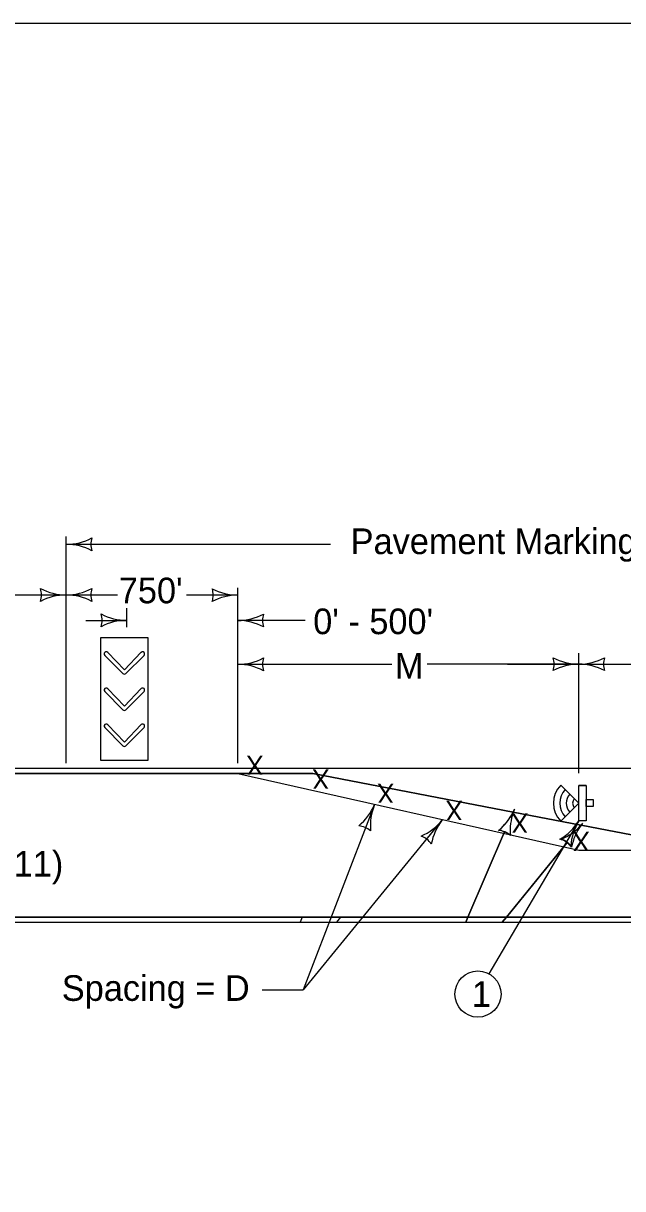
# Model space of a CAD drawing. Extents: x -2135039 to 114557, y -2139150 to -409929.
# Drawn here: x -2133449 to -2132982, y -2137945 to -2137036 of the extents above; entities that cross this region are included whole.
import ezdxf

# ---------------------------------------------------------------- set-up
doc = ezdxf.new("R2010")
doc.units = 0
for name, color, linetype in [('dsnStdLabel', 7, 'Continuous'), ('dsnStdLineWork', 7, 'Continuous'), ('dsnStdShading', 7, 'Continuous'), ('Level 1', 7, 'Continuous'), ('Level 2', 7, 'Continuous'), ('StdDimension', 7, 'Continuous')]:
    doc.layers.add(name, color=color, linetype=linetype)

msp = doc.modelspace()

# ---------------------------------------------------------------- linework, layer by layer
at = {"layer": 'dsnStdLabel'}
for p, q in [((-2133369.21, -2137542.89), (-2133355.12, -2137528.8)), ((-2133369.21, -2137571.13), (-2133355.12, -2137557.04)), ((-2133369.21, -2137599.19), (-2133355.12, -2137585.1)), ((-2133010.55, -2137630.23), (-2133010.55, -2137657.73))]:
    msp.add_line(p, q, dxfattribs=at)
for points in [[(-2133352.04, -2137514.75), (-2133352.04, -2137610.75), (-2133388.75, -2137610.75), (-2133388.75, -2137514.75)], [(-2133016.17, -2137657.73), (-2133016.17, -2137630.23), (-2133010.55, -2137630.23), (-2133010.55, -2137657.73)], [(-2133010.55, -2137646.68), (-2133010.55, -2137641.06), (-2133004.92, -2137641.06), (-2133004.92, -2137646.68)]]:
    msp.add_lwpolyline(points, close=True, dxfattribs=at)
for points in [[(-2133385.7, -2137528.77), (-2133385.65, -2137528.82), (-2133371.57, -2137542.9), (-2133371.55, -2137542.92)], [(-2133357.44, -2137526.46), (-2133357.5, -2137526.53), (-2133370.4, -2137540.1), (-2133383.3, -2137526.51)], [(-2133385.7, -2137557), (-2133385.65, -2137557.05), (-2133371.57, -2137571.14), (-2133371.55, -2137571.15)], [(-2133357.44, -2137554.7), (-2133357.5, -2137554.76), (-2133370.4, -2137568.33), (-2133383.3, -2137554.75)], [(-2133385.7, -2137585.07), (-2133385.65, -2137585.12), (-2133371.57, -2137599.2), (-2133371.55, -2137599.22)], [(-2133357.44, -2137582.76), (-2133357.5, -2137582.83), (-2133370.4, -2137596.4), (-2133383.3, -2137582.81)]]:
    msp.add_lwpolyline(points, dxfattribs=at)
for centre, start, end in [((-2133384.51, -2137527.63), 42.63982, 223.799), ((-2133356.28, -2137527.63), 314.71897, 134.90254), ((-2133370.4, -2137541.75), 225.39017, 315.83844), ((-2133384.51, -2137555.86), 42.63982, 223.799), ((-2133356.28, -2137555.86), 314.71897, 134.90254), ((-2133370.4, -2137569.98), 225.39017, 315.83844), ((-2133384.51, -2137583.93), 42.63982, 223.799), ((-2133356.28, -2137583.93), 314.71897, 134.90254), ((-2133370.4, -2137598.05), 225.39017, 315.83844)]:
    msp.add_arc(centre, 1.65, start, end, dxfattribs=at)
at = {"layer": 'dsnStdLineWork'}
for p, q in [((-2134890.21, -2137620.91), (-2133281.94, -2137620.91)), ((-2133281.94, -2137620.91), (-2133016.17, -2137680.64)), ((-2133016.17, -2137680.64), (-2132867.99, -2137680.64)), ((-2134898.17, -2137732.92), (-2132869.81, -2137732.92))]:
    msp.add_line(p, q, dxfattribs=at)
at = {"layer": 'dsnStdShading'}
for p, q in [((-2132633.8, -2137616.91), (-2133464.46, -2137616.91)), ((-2133223.54, -2137620.91), (-2133464.46, -2137620.91)), ((-2133464.46, -2137620.91), (-2133223.54, -2137620.91)), ((-2133067.38, -2137650.93), (-2133223.54, -2137620.91)), ((-2133223.54, -2137620.91), (-2133067.38, -2137650.93)), ((-2133067.24, -2137650.96), (-2133014.49, -2137661.1)), ((-2133014.49, -2137661.1), (-2133067.24, -2137650.96)), ((-2133073.99, -2137666.4), (-2133102.64, -2137732.92)), ((-2133102.63, -2137732.91), (-2133073.99, -2137666.4)), ((-2133014.39, -2137661.12), (-2132912.87, -2137680.64)), ((-2132912.87, -2137680.64), (-2133014.39, -2137661.12)), ((-2133072.64, -2137732.92), (-2133025.35, -2137674.56)), ((-2133025.35, -2137674.56), (-2133072.64, -2137732.92)), ((-2133102.63, -2137732.91), (-2134898.19, -2137732.91)), ((-2134894.19, -2137736.9), (-2133075.86, -2137736.9)), ((-2134894.19, -2137736.91), (-2133104.35, -2137736.9)), ((-2133680.95, -2137732.91), (-2133102.63, -2137732.91)), ((-2133231.88, -2137732.91), (-2133233.49, -2137736.9)), ((-2133233.49, -2137736.9), (-2133204.94, -2137736.9)), ((-2133201.81, -2137732.91), (-2133231.88, -2137732.91)), ((-2133204.94, -2137736.9), (-2133201.81, -2137732.91)), ((-2133104.35, -2137736.9), (-2133102.63, -2137732.91)), ((-2133102.63, -2137732.91), (-2133104.35, -2137736.9)), ((-2133104.35, -2137736.9), (-2133075.86, -2137736.9)), ((-2133102.64, -2137732.92), (-2133072.64, -2137732.92)), ((-2133072.62, -2137732.91), (-2133102.63, -2137732.91)), ((-2133072.62, -2137732.91), (-2133075.86, -2137736.9)), ((-2133075.86, -2137736.9), (-2133072.62, -2137732.91)), ((-2133075.86, -2137736.9), (-2132839.34, -2137736.9)), ((-2132836.36, -2137732.91), (-2133072.62, -2137732.91))]:
    msp.add_line(p, q, dxfattribs=at)
for points in [[(-2133066.76, -2137649.6), (-2133066.39, -2137648.74), (-2133066.39, -2137648.74)], [(-2133066.74, -2137649.61), (-2133066.76, -2137649.6)], [(-2133014.39, -2137661.12), (-2133014.49, -2137661.1)], [(-2133013.65, -2137660.12), (-2133013.26, -2137659.63), (-2133013.25, -2137659.63)], [(-2133072.64, -2137732.92), (-2132863.84, -2137732.92), (-2132768.77, -2137732.92)]]:
    msp.add_lwpolyline(points, dxfattribs=at)
for centre, radius, start, end in [((-2133105.61, -2137632.37), 42.5, 309.26549, 336.07196), ((-2133105.61, -2137632.37), 42.5, 334.0959, 336.07196), ((-2133027.17, -2137665.12), 42.5, 157.35558, 160.5422), ((-2133027.17, -2137665.12), 42.5, 158.60338, 160.5422), ((-2133105.61, -2137632.37), 42.5, 337.32038, 337.33798), ((-2133105.61, -2137632.37), 42.5, 309.26549, 334.0959), ((-2133027.17, -2137665.12), 42.5, 160.5422, 185.41047), ((-2133027.17, -2137665.12), 42.5, 160.5422, 185.41047), ((-2133080.12, -2137681.62), 16.42, 68.07923, 85.07133), ((-2133080.12, -2137681.62), 16.42, 49.60463, 85.07133), ((-2133080.12, -2137681.62), 16.42, 49.60463, 68.07923), ((-2133046.47, -2137633.12), 42.5, 293.33927, 318.82188), ((-2133046.47, -2137633.12), 42.5, 293.33927, 318.82188), ((-2132980.04, -2137686.14), 42.5, 143.94153, 169.48425), ((-2132980.04, -2137686.14), 42.5, 143.94153, 169.48425), ((-2133046.47, -2137633.12), 42.5, 318.82188, 320.56149), ((-2132980.04, -2137686.14), 42.5, 141.42936, 143.94153), ((-2133046.47, -2137633.12), 42.5, 321.39416, 321.41176), ((-2133035.48, -2137687.48), 16.42, 51.90955, 69.14511), ((-2133035.48, -2137687.48), 16.42, 33.67841, 69.14511), ((-2133035.48, -2137687.48), 16.42, 33.67841, 51.90955)]:
    msp.add_arc(centre, radius, start, end, dxfattribs=at)
at = {"layer": 'Level 1'}
msp.add_lwpolyline([(-2134934.44, -2137035.95), (-2131799.45, -2137035.95), (-2131799.45, -2139045.94), (-2134934.44, -2139045.94)], close=True, dxfattribs=at)
msp.add_circle((-2133094.8, -2137792.82), 18, dxfattribs=at)
at = {"layer": 'Level 2'}
for p, q in [((-2133030.31, -2137629.84), (-2133016.17, -2137643.98)), ((-2133010.55, -2137630.23), (-2133016.17, -2137630.23)), ((-2133016.17, -2137643.98), (-2133030.31, -2137658.13)), ((-2133010.55, -2137657.73), (-2133016.17, -2137657.73))]:
    msp.add_line(p, q, dxfattribs=at)
for radius, start, end in [(20.32, 135.88004, 224.03126), (15.33, 136.16647, 223.71595), (10.34, 136.72938, 223.09626), (5.32, 138.70055, 221.29945)]:
    msp.add_arc((-2133015.71, -2137644.01), radius, start, end, dxfattribs=at)
at = {"layer": 'StdDimension'}
for p, q in [((-2133415.82, -2137612.78), (-2133415.82, -2137436.14)), ((-2133209.84, -2137442.2), (-2133415.75, -2137442.2)), ((-2133281.94, -2137612.78), (-2133281.94, -2137476.08)), ((-2133518.81, -2137481.63), (-2133415.82, -2137481.63)), ((-2133415.82, -2137481.63), (-2133375.82, -2137481.63)), ((-2133321.94, -2137481.63), (-2133281.94, -2137481.63)), ((-2133368.51, -2137506.74), (-2133368.51, -2137491.89)), ((-2133400.51, -2137501.44), (-2133368.51, -2137501.44)), ((-2133229.48, -2137501.58), (-2133281.94, -2137501.58)), ((-2133016.17, -2137620.62), (-2133016.17, -2137527.11)), ((-2133161.94, -2137535.77), (-2133281.94, -2137535.77)), ((-2133014.43, -2137535.62), (-2133134.43, -2137535.62)), ((-2133071.76, -2137535.62), (-2132954.92, -2137535.62)), ((-2133175.4, -2137645.14), (-2133230.93, -2137789.63)), ((-2133122.61, -2137657.11), (-2133230.93, -2137789.63)), ((-2133016.17, -2137657.73), (-2133086.25, -2137776.98)), ((-2133262.93, -2137789.63), (-2133230.93, -2137789.63))]:
    msp.add_line(p, q, dxfattribs=at)
for centre, radius, start, end in [((-2133415.75, -2137399.7), 42.5, 270, 298.07249), ((-2133380.12, -2137442.2), 16.42, 162.26665, 197.73335), ((-2133415.75, -2137484.7), 42.5, 61.92751, 90), ((-2133451.45, -2137481.63), 16.42, 342.26665, 17.73335), ((-2133415.82, -2137439.13), 42.5, 241.92751, 270), ((-2133415.82, -2137439.13), 42.5, 270, 298.07249), ((-2133380.18, -2137481.63), 16.42, 162.26665, 197.73335), ((-2133317.58, -2137481.76), 16.42, 342.26665, 17.73335), ((-2133281.94, -2137439.26), 42.5, 241.92751, 270), ((-2133415.82, -2137524.13), 42.5, 90, 118.07249), ((-2133415.82, -2137524.13), 42.5, 61.92751, 90), ((-2133281.94, -2137524.26), 42.5, 90, 118.07249), ((-2133404.15, -2137501.44), 16.42, 342.26665, 17.73335), ((-2133368.51, -2137458.94), 42.5, 241.92751, 270), ((-2133368.51, -2137543.94), 42.5, 90, 118.07249), ((-2133281.94, -2137459.08), 42.5, 270, 298.07249), ((-2133281.94, -2137544.08), 42.5, 61.92751, 90), ((-2133246.31, -2137501.58), 16.42, 162.26665, 197.73335), ((-2133281.94, -2137493.27), 42.5, 270, 298.07249), ((-2133246.31, -2137535.77), 16.42, 162.26665, 197.73335), ((-2133051.81, -2137535.62), 16.42, 342.26665, 17.73335), ((-2133016.17, -2137493.12), 42.5, 241.92751, 270), ((-2133016.17, -2137493.12), 42.5, 270, 298.07249), ((-2132980.54, -2137535.62), 16.42, 162.26665, 197.73335), ((-2133281.94, -2137578.27), 42.5, 61.92751, 90), ((-2133016.17, -2137578.12), 42.5, 90, 118.07249), ((-2133016.17, -2137578.12), 42.5, 61.92751, 90), ((-2133214.62, -2137628.77), 42.5, 309.26549, 337.33798), ((-2133136.18, -2137661.52), 42.5, 157.33798, 185.41047), ((-2133155.83, -2137630.6), 42.5, 293.33927, 321.41176), ((-2133089.39, -2137683.62), 42.5, 141.41176, 169.48425), ((-2133052.35, -2137635.44), 42.5, 300.28549, 328.35798), ((-2132979.99, -2137680.03), 42.5, 148.35798, 176.43047), ((-2133189.13, -2137678.03), 16.42, 49.60463, 85.07133), ((-2133144.84, -2137684.96), 16.42, 33.67841, 69.14511), ((-2133034.87, -2137688.07), 16.42, 40.62462, 76.09133)]:
    msp.add_arc(centre, radius, start, end, dxfattribs=at)

# ---------------------------------------------------------------- texts
at = {"layer": 'dsnStdLabel'}
for p in [(-2133261.99, -2137606.86), (-2133210.64, -2137617.61), (-2133160.07, -2137628.72), (-2133106.64, -2137642.07), (-2133055.51, -2137651.99), (-2133007.72, -2137666.2)]:
    msp.add_text('X', height=15, rotation=180, dxfattribs=at).set_placement(p)
msp.add_text('(See PM-111)', height=20, dxfattribs=at).set_placement((-2133584.5, -2137701.21))
at = {"layer": 'Level 1'}
msp.add_text('1', height=20, dxfattribs=at).set_placement((-2133099.55, -2137802.82))
at = {"layer": 'StdDimension'}
for s, p in [('Pavement Marking Removal Limits', (-2133194.03, -2137449.79)), ("750'", (-2133374.78, -2137488.17)), ("0' - 500'", (-2133223.23, -2137512.23)), ('M', (-2133159.56, -2137546.9)), ('Spacing = D', (-2133419.2, -2137798.14))]:
    msp.add_text(s, height=20, dxfattribs=at).set_placement(p)

doc.saveas('drawing.dxf')
